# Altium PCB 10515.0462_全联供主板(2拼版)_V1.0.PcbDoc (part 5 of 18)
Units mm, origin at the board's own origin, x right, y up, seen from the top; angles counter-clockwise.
Board outline 282 x 198 mm, 2 copper layers (Top Layer, Bottom Layer); 716 components, 0 nets, 2364 pads, 1800 vias.
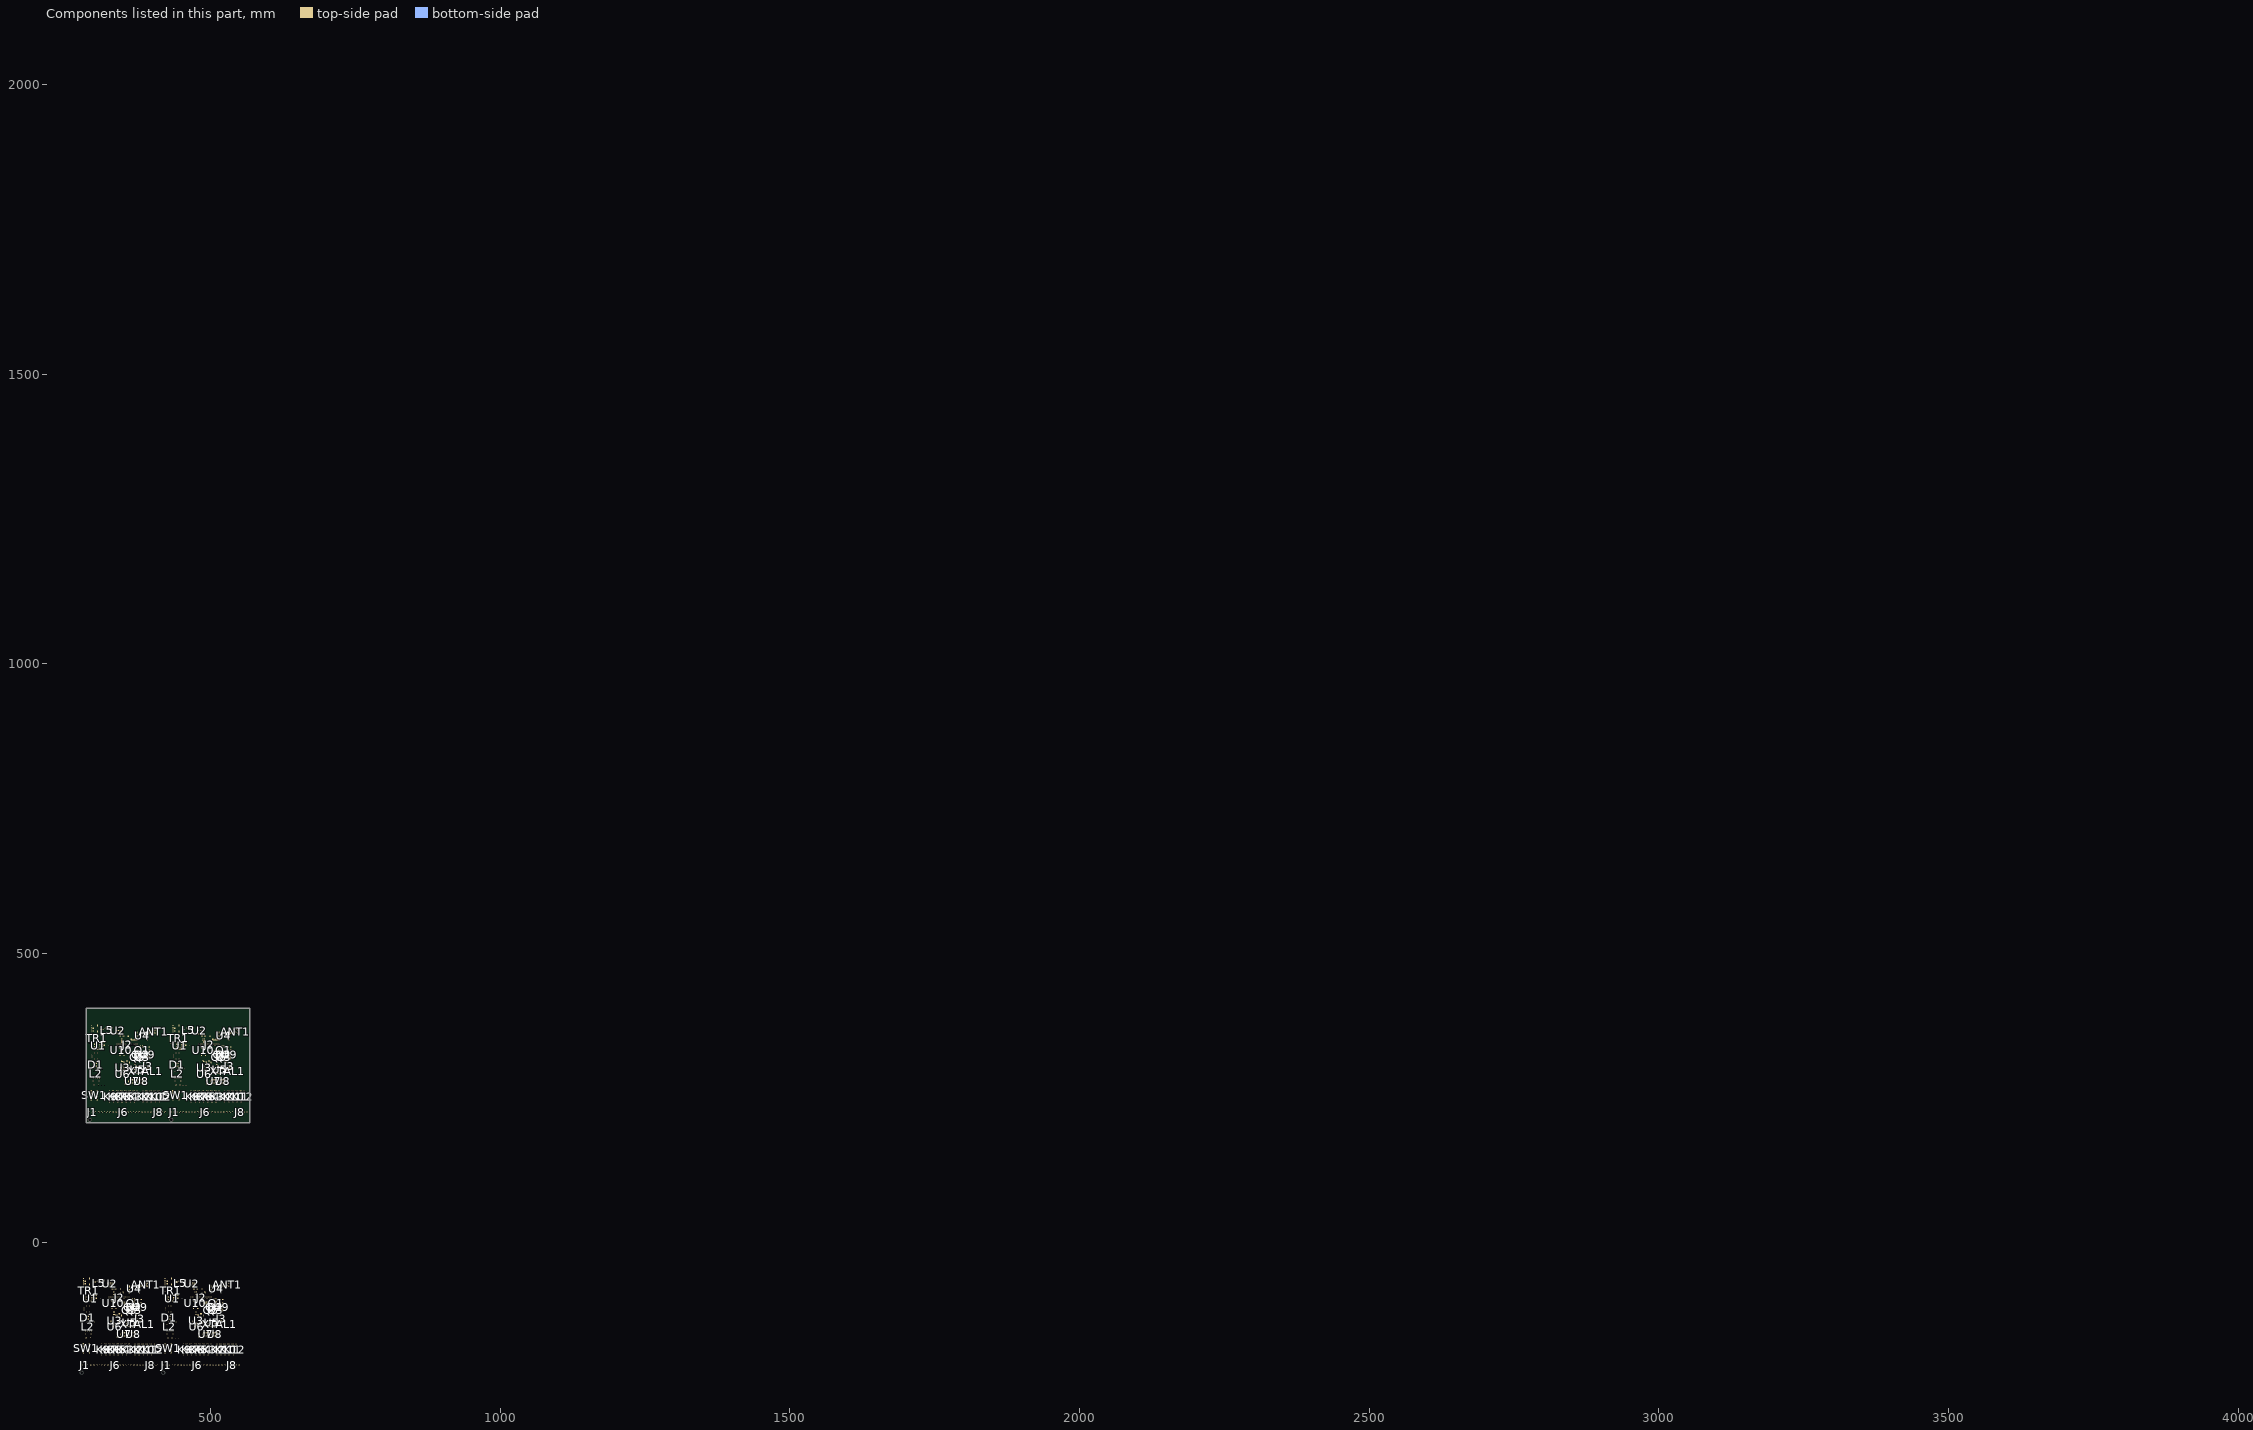
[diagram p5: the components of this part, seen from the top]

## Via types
v1: diameter 0.7, hole 0.4, Top Layer to Bottom Layer, tented both sides, 1800 vias

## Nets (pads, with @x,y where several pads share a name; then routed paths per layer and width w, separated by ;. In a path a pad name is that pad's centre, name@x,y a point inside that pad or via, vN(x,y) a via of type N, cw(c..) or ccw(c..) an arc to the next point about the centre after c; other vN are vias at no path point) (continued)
copper on no net: (continued)
  Top Layer w0.2: 520.272,290.998 ccw(c520.593,291.319) 520.593,290.864 ; 520.328,290.941 cw(c519.945,290.558) 520.487,290.558 ; 520.369,290.9 519.861,291.408 519.099,291.408 518.901,291.607 518.901,292.674 518.901,294.258 519.716,295.074 521.301,295.074 520.732,295.074 ; 520.886,-119.119 cw(c520.363,-119.642) 521.103,-119.642 cw(c521.842,-119.642) 521.319,-119.119 ; v1@521.008,303.473 ccw(c520.404,303.473) 520.831,303.9 ccw(c521.258,304.327) v1@521.258,303.723 ; 521.242,282.672 ccw(c520.815,283.099) 521.419,283.099 ccw(c522.022,283.099) 521.596,282.672 ; 521.301,297.074 524.251,297.074 525.673,295.652 525.991,295.652 526.054,295.652 526.753,296.35 529.674,296.35 529.999,296.025 ; 521.301,297.574 525.719,297.574 ; 521.301,298.074 525.36,298.074 527.411,300.125 527.411,304.577 528.144,305.31 ; 521.301,298.574 525.295,298.574 527.011,300.29 527.011,306.521 527.392,306.902 529.259,306.902 529.532,307.175 529.532,315.284 529.786,315.538 534.339,315.538 534.731,315.931 534.731,317.731 ; 521.301,299.074 525.229,299.074 526.611,300.456 526.611,306.775 527.138,307.302 528.878,307.302 529.132,307.556 529.132,318.84 529.673,319.382 ; 521.301,299.574 525.163,299.574 526.211,300.622 526.211,307.41 526.503,307.702 528.37,307.702 528.732,308.064 528.732,319.456 529.513,320.237 v1(529.513,320.491) ; 521.301,300.074 525.097,300.074 525.811,300.787 525.811,307.645 526.445,308.28 526.445,311.564 ; 521.301,301.074 523.089,301.074 523.329,301.314 523.329,302.603 524.036,303.31 ; 521.301,301.574 522.533,301.574 522.929,301.97 522.929,310.311 522.911,310.329 522.911,314.688 523.488,315.265 527.335,315.265 528.224,316.155 528.224,320.536 528.243,320.555 ; 521.301,302.074 522.11,302.074 522.405,302.369 522.405,303.083 522.401,303.087 522.401,315.03 523.163,315.792 526.465,315.792 526.846,316.173 526.846,320.555 ; 521.301,302.574 521.617,302.574 521.997,302.954 ; 521.929,-133.345 ccw(c521.076,-132.491) 522.283,-132.491 ccw(c523.49,-132.491) 522.637,-133.345 ; 521.966,302.084 ccw(c521.966,302.456) 522.229,302.193 ; 521.974,302.58 cw(c522.197,302.754) 521.997,302.954 ; 522.029,-131.644 cw(c521.416,-132.258) 522.283,-132.258 ; 522.071,-133.486 ccw(c521.559,-132.974) 522.283,-132.974 ccw(c523.007,-132.974) 522.495,-133.486 ; 522.283,-133.571 522.283,-131.517 ; 522.283,-133.378 cw(c524.735,-133.378) 523.001,-131.644 ; 522.283,-132.895 cw(c524.252,-132.895) 522.86,-131.503 ; 522.283,-132.412 cw(c523.769,-132.412) 522.718,-131.362 ; 522.283,-131.93 cw(c523.286,-131.93) 522.577,-131.22 ; 522.413,-71.827 522.554,-71.967 522.579,-71.942 ; 522.512,282.672 ccw(c522.085,283.099) 522.689,283.099 ccw(c523.292,283.099) 522.866,282.672 ; v1@523.417,-74.482 v1@523.631,-74.482 ; 523.448,302.722 cw(c524.036,302.133) 524.036,302.965 ; 523.54,302.814 ccw(c523.082,303.272) 523.729,303.272 ; 523.819,301.404 cw(c523.603,301.187) 523.909,301.187 ; 523.909,300.818 cw(c524.562,300.818) 524.204,301.364 ; 523.909,301.188 cw(c524.319,301.188) 524.094,301.532 ; 524.421,313.215 526.445,313.215 ; 524.688,297.574 cw(c524.688,296.037) 525.774,297.124 ; 524.771,312.965 cw(c525.375,312.361) 525.375,313.215 ; 524.771,313.439 ccw(c525.311,313.978) 525.311,313.215 ; 524.861,296.464 ccw(c525.991,297.594) 525.991,295.996 ccw(c525.991,296.981) 526.687,296.285 ; 524.913,312.823 cw(c525.858,311.878) 525.858,313.215 ; 524.913,313.58 ccw(c525.794,314.461) 525.794,313.215 ; 525.038,325.317 525.356,325 ; 525.17,297.574 cw(c525.17,296.52) 525.916,297.265 ; 525.202,296.123 ccw(c525.991,296.911) 525.991,295.796 ccw(c525.991,296.298) 526.346,295.943 ; 525.544,295.781 ccw(c525.991,296.229) 525.991,295.596 ; 525.653,297.574 cw(c525.653,297.003) 526.057,297.407 ; 525.917,-74.482 526.033,-74.482 ; 526.228,311.309 cw(c525.705,310.786) 526.445,310.786 cw(c527.185,310.786) 526.662,311.309 ; 526.228,312.998 ccw(c525.705,312.475) 525.705,313.215 ccw(c525.705,313.955) 526.228,313.432 ; 526.297,295.69 cw(c526.792,295.69) 526.442,296.039 ; 526.437,322.933 cw(c525.697,322.194) 526.74,322.114 ; 526.629,320.162 cw(c526.106,319.639) 526.846,319.639 cw(c527.586,319.639) 527.063,320.162 ; 526.744,322.625 cw(c526.269,322.15) 526.939,322.099 ; 526.754,322.398 ccw(c526.714,322.523) 526.846,322.523 ccw(c526.978,322.523) 526.938,322.398 ; 527.411,301.303 528.841,301.303 ; 528.026,320.162 cw(c527.548,319.684) 528.224,319.684 ; 528.042,322.337 ccw(c527.66,322.777) 528.243,322.777 ccw(c528.826,322.777) 528.444,322.337 ; 528.224,319.594 cw(c529.028,319.594) 528.46,320.162 ; 528.587,301.086 ccw(c528.063,300.563) 528.063,301.303 ccw(c528.063,302.043) 528.587,301.52 ; 529.212,318.92 cw(c529.987,318.145) 530.077,319.238 ; 529.517,319.226 cw(c530.034,318.709) 530.094,319.437 ; 529.793,319.294 ccw(c529.674,319.258) 529.674,319.382 ; 529.793,319.471 cw(c529.674,319.507) 529.674,319.382 ; 529.819,295.758 ccw(c529.711,296.025) 529.999,296.025 ; v1@529.916,316.625 cw(c529.554,316.235) 530.086,316.235 ; 529.999,295.193 529.999,296.025 ; v1(530.086,316.808) 530.086,316.235 ; 530.086,319.382 529.673,319.382 ; 530.178,295.758 cw(c530.287,296.025) 529.999,296.025 ; v1@530.256,316.625 ccw(c530.618,316.235) 530.086,316.235 ; 530.53,301.341 530.492,301.303 532.277,301.303 ; 530.53,302.947 530.53,303.074 ; 530.656,348.23 cw(c533.417,348.23) 531.465,350.183 ; 530.656,348.713 cw(c532.935,348.713) 531.323,350.324 ; 530.656,349.196 cw(c532.452,349.196) 531.182,350.465 ; 530.656,349.678 cw(c531.969,349.678) 531.04,350.607 ; 530.747,301.086 cw(c531.27,300.563) 531.27,301.303 cw(c531.27,302.043) 530.747,301.52 ; 530.788,350.395 cw(c530.29,350.305) 530.648,349.948 cw(c530.986,349.609) 531.093,350.076 ; 530.833,352.27 ccw(c530.499,352.082) 530.499,352.465 ; 530.833,352.661 cw(c530.499,352.849) 530.499,352.465 ; 530.899,354.183 ccw(c530.216,353.5) 530.216,354.465 ccw(c530.216,355.431) 530.899,354.748 ; 530.899,356.183 ccw(c530.216,355.5) 530.216,356.465 ccw(c530.216,357.431) 530.899,356.748 ; 531.632,352.465 530.499,352.465 ; 531.632,354.465 530.213,354.465 529.767,354.019 529.767,347.288 529.132,346.653 493.572,346.653 493.11,346.191 493.11,345.175 ; 532.023,301.086 ccw(c531.499,300.563) 531.499,301.303 ccw(c531.499,302.043) 532.023,301.52 ; 532.312,302.838 532.312,302.897 532.312,303.024 ; 532.966,317.476 cw(c532.443,316.953) 533.183,316.953 cw(c533.923,316.953) 533.4,317.476 ; 533.183,317.731 533.183,316.415 532.815,316.046 530.275,316.046 530.086,316.235 ; 534.515,317.476 cw(c533.992,316.953) 534.731,316.953 cw(c535.471,316.953) 534.948,317.476 ; 535.558,303.251 ccw(c534.705,304.104) 535.912,304.104 ccw(c537.119,304.104) 536.265,303.251 ; 535.658,304.951 cw(c535.044,304.338) 535.912,304.338 ; 535.7,303.109 ccw(c535.188,303.621) 535.912,303.621 ccw(c536.636,303.621) 536.124,303.109 ; 535.912,303.024 535.912,305.078 ; 535.912,303.217 cw(c538.363,303.217) 536.63,304.951 ; 535.912,303.7 cw(c537.881,303.7) 536.488,305.092 ; 535.912,304.183 cw(c537.398,304.183) 536.347,305.234 ; 535.912,304.666 cw(c536.915,304.666) 536.206,305.375 ; 536.042,364.769 536.182,364.628 536.208,364.654 ; v1@537.046,362.114 v1@537.26,362.114 ; 539.546,362.114 539.661,362.114 ; 323.841,-72.151 324.211,-71.781 ; 325.095,-68.992 325.276,-68.811 ; 338.724,367.603 338.905,367.785 ; 340.721,-110.77 ccw(c340.556,-110.77) 340.622,-110.618 cw(c340.556,-110.77) 340.721,-110.77 ; 340.721,-110.77 cw(c340.886,-110.77) 340.821,-110.618 ccw(c340.886,-110.77) 340.721,-110.77 ; 354.35,325.826 ccw(c354.185,325.826) 354.25,325.977 cw(c354.185,325.826) 354.35,325.826 ; 354.35,325.826 cw(c354.515,325.826) 354.449,325.977 ccw(c354.515,325.826) 354.35,325.826 ; 464.841,-72.151 465.211,-71.781 ; 466.095,-68.992 466.277,-68.811 ; 479.724,367.603 479.905,367.785 ; 481.721,-110.77 ccw(c481.556,-110.77) 481.622,-110.618 cw(c481.556,-110.77) 481.721,-110.77 ; 481.721,-110.77 cw(c481.886,-110.77) 481.821,-110.618 ccw(c481.886,-110.77) 481.721,-110.77 ; 495.35,325.826 ccw(c495.185,325.826) 495.25,325.977 cw(c495.185,325.826) 495.35,325.826 ; 495.35,325.826 cw(c495.515,325.826) 495.449,325.977 ccw(c495.515,325.826) 495.35,325.826
  Top Layer w0.3: v1@339.183,-110.53 cw(c338.841,-110.872) 339.324,-110.872 cw(c339.807,-110.872) v1@339.466,-110.53 ; v1(339.324,-110.389) 339.324,-113.183 339.832,-113.691 347.96,-113.691 348.341,-114.072 v1(348.341,-129.439) ; 346.182,-102.105 346.436,-101.851 346.436,-94.26 ; 346.246,-101.76 ccw(c345.787,-101.301) 346.436,-101.301 ; 346.436,-101.344 ccw(c347.025,-101.344) 346.609,-101.76 ; 346.829,-93.273 cw(c345.486,-93.31) 346.436,-94.26 ; 347.194,-96.305 cw(c346.596,-96.902) 347.441,-96.902 cw(c348.286,-96.902) 347.688,-96.305 ; 347.424,-93.867 ccw(c347.386,-95.21) 346.436,-94.26 ; 347.441,-95.795 347.441,-100.726 347.706,-100.991 349.611,-100.991 349.981,-101.361 ; 347.441,-93.255 346.436,-94.26 ; v1@348.2,-129.298 ccw(c347.858,-128.956) 348.341,-128.956 ccw(c348.824,-128.956) v1@348.483,-129.298 ; 349.369,-93.255 cw(c347.892,-93.255) 348.936,-94.3 cw(c349.981,-95.345) 349.981,-93.867 ; 349.548,-96.228 cw(c348.504,-97.273) 349.981,-97.273 cw(c351.459,-97.273) 350.414,-96.228 ; 349.808,-101.752 ccw(c349.452,-101.361) 349.981,-101.361 ; 349.981,-101.941 349.981,-101.361 ; 349.981,-95.795 349.981,-99.583 350.246,-99.848 356.342,-99.848 356.723,-100.229 356.723,-108.593 355.551,-109.765 ; 349.981,-93.255 348.722,-94.514 348.722,-100.229 348.976,-100.483 353.167,-100.483 353.45,-100.766 353.45,-101.941 ; 350.154,-101.752 cw(c350.51,-101.361) 349.981,-101.361 ; v1@352.811,326.065 cw(c352.47,325.724) 352.953,325.724 cw(c353.436,325.724) v1@353.094,326.065 ; v1(352.953,326.206) 352.953,323.412 353.461,322.904 361.589,322.904 361.97,322.523 v1(361.97,307.156) ; 353.269,-101.76 ccw(c352.831,-101.322) 353.45,-101.322 ccw(c354.069,-101.322) 353.632,-101.76 ; 355.589,-109.509 ccw(c355.589,-108.982) 355.961,-109.355 ; 355.845,-109.765 cw(c356.556,-109.765) 356.053,-109.263 ; 359.811,334.491 360.065,334.745 360.065,342.335 ; 359.875,334.835 ccw(c359.416,335.294) 360.065,335.294 ; 360.065,335.252 ccw(c360.654,335.252) 360.237,334.835 ; 360.458,343.323 cw(c359.115,343.285) 360.065,342.335 ; 360.822,340.291 cw(c360.225,339.693) 361.07,339.693 cw(c361.915,339.693) 361.317,340.291 ; 361.053,342.728 ccw(c361.015,341.385) 360.065,342.335 ; 361.07,340.8 361.07,335.87 361.335,335.604 363.24,335.604 363.61,335.235 ; 361.07,343.34 360.065,342.335 ; v1@361.828,307.298 ccw(c361.487,307.639) 361.97,307.639 ccw(c362.453,307.639) v1@362.111,307.298 ; 362.998,343.34 cw(c361.52,343.34) 362.565,342.295 cw(c363.61,341.251) 363.61,342.728 ; 363.177,340.367 cw(c362.132,339.323) 363.61,339.323 cw(c365.087,339.323) 364.043,340.367 ; 363.437,334.844 ccw(c363.081,335.235) 363.61,335.235 ; 363.61,334.654 363.61,335.235 ; 363.61,340.8 363.61,337.013 363.875,336.747 369.971,336.747 370.352,336.366 370.352,328.003 369.179,326.83 ; 363.61,343.34 362.351,342.081 362.351,336.366 362.605,336.112 366.796,336.112 367.079,335.829 367.079,334.654 ; 363.782,334.844 cw(c364.139,335.235) 363.61,335.235 ; 366.898,334.835 ccw(c366.46,335.273) 367.079,335.273 ccw(c367.698,335.273) 367.26,334.835 ; 369.217,327.086 ccw(c369.217,327.613) 369.59,327.241 ; 369.474,326.83 cw(c370.185,326.83) 369.682,327.333 ; v1@480.183,-110.53 cw(c479.841,-110.872) 480.324,-110.872 cw(c480.807,-110.872) v1@480.466,-110.53 ; v1(480.324,-110.389) 480.324,-113.183 480.832,-113.691 488.96,-113.691 489.341,-114.072 v1(489.341,-129.439) ; 487.182,-102.105 487.436,-101.851 487.436,-94.26 ; 487.246,-101.76 ccw(c486.787,-101.301) 487.436,-101.301 ; 487.436,-101.344 ccw(c488.025,-101.344) 487.609,-101.76 ; 487.829,-93.273 cw(c486.486,-93.31) 487.436,-94.26 ; 488.194,-96.305 cw(c487.596,-96.902) 488.441,-96.902 cw(c489.286,-96.902) 488.688,-96.305 ; 488.424,-93.867 ccw(c488.386,-95.21) 487.436,-94.26 ; 488.441,-95.795 488.441,-100.726 488.706,-100.991 490.611,-100.991 490.981,-101.361 ; 488.441,-93.255 487.436,-94.26 ; v1@489.2,-129.298 ccw(c488.858,-128.956) 489.341,-128.956 ccw(c489.824,-128.956) v1@489.483,-129.298 ; 490.369,-93.255 cw(c488.892,-93.255) 489.936,-94.3 cw(c490.981,-95.345) 490.981,-93.867 ; 490.548,-96.228 cw(c489.504,-97.273) 490.981,-97.273 cw(c492.459,-97.273) 491.414,-96.228 ; 490.808,-101.752 ccw(c490.452,-101.361) 490.981,-101.361 ; 490.981,-101.941 490.981,-101.361 ; 490.981,-95.795 490.981,-99.583 491.246,-99.848 497.342,-99.848 497.723,-100.229 497.723,-108.593 496.551,-109.765 ; 490.981,-93.255 489.722,-94.514 489.722,-100.229 489.976,-100.483 494.167,-100.483 494.45,-100.766 494.45,-101.941 ; 491.154,-101.752 cw(c491.51,-101.361) 490.981,-101.361 ; v1@493.811,326.065 cw(c493.47,325.724) 493.953,325.724 cw(c494.436,325.724) v1@494.094,326.065 ; v1(493.953,326.206) 493.953,323.412 494.461,322.904 502.589,322.904 502.97,322.523 v1(502.97,307.156) ; 494.269,-101.76 ccw(c493.831,-101.322) 494.45,-101.322 ccw(c495.069,-101.322) 494.632,-101.76 ; 496.589,-109.509 ccw(c496.589,-108.982) 496.961,-109.355 ; 496.845,-109.765 cw(c497.556,-109.765) 497.053,-109.263 ; 500.811,334.491 501.065,334.745 501.065,342.335 ; 500.875,334.835 ccw(c500.416,335.294) 501.065,335.294 ; 501.065,335.252 ccw(c501.654,335.252) 501.237,334.835 ; 501.458,343.323 cw(c500.115,343.285) 501.065,342.335 ; 501.822,340.291 cw(c501.225,339.693) 502.07,339.693 cw(c502.915,339.693) 502.317,340.291 ; 502.053,342.728 ccw(c502.015,341.385) 501.065,342.335 ; 502.07,340.8 502.07,335.87 502.335,335.604 504.24,335.604 504.61,335.235 ; 502.07,343.34 501.065,342.335 ; v1@502.828,307.298 ccw(c502.487,307.639) 502.97,307.639 ccw(c503.453,307.639) v1@503.111,307.298 ; 503.998,343.34 cw(c502.52,343.34) 503.565,342.295 cw(c504.61,341.251) 504.61,342.728 ; 504.177,340.367 cw(c503.132,339.323) 504.61,339.323 cw(c506.087,339.323) 505.043,340.367 ; 504.437,334.844 ccw(c504.081,335.235) 504.61,335.235 ; 504.61,334.654 504.61,335.235 ; 504.61,340.8 504.61,337.013 504.875,336.747 510.971,336.747 511.352,336.366 511.352,328.003 510.179,326.83 ; 504.61,343.34 503.351,342.081 503.351,336.366 503.605,336.112 507.796,336.112 508.079,335.829 508.079,334.654 ; 504.782,334.844 cw(c505.139,335.235) 504.61,335.235 ; 507.898,334.835 ccw(c507.46,335.273) 508.079,335.273 ccw(c508.698,335.273) 508.26,334.835 ; 510.217,327.086 ccw(c510.217,327.613) 510.59,327.241 ; 510.474,326.83 cw(c511.185,326.83) 510.682,327.333
  Top Layer w0.4: 327.204,-70.942 327.613,-70.942 328.578,-71.908 328.578,-72.605 ; 327.204,-68.992 328.098,-68.098 330.434,-68.098 330.801,-68.465 330.801,-69.153 ; 327.604,-68.992 cw(c328.57,-68.992) 327.887,-68.309 ; 328.433,-72.459 ccw(c328.08,-72.107) 328.578,-72.107 ccw(c329.077,-72.107) 328.724,-72.459 ; 330.655,-68.969 ccw(c330.303,-68.617) 330.801,-68.617 ccw(c331.299,-68.617) 330.947,-68.969 ; 340.833,365.653 341.241,365.653 342.207,364.687 342.207,363.99 ; 340.833,367.603 341.727,368.497 344.063,368.497 344.43,368.131 344.43,367.442 ; 341.233,367.603 cw(c342.198,367.603) 341.516,368.286 ; 342.061,364.136 ccw(c341.709,364.489) 342.207,364.489 ccw(c342.706,364.489) 342.353,364.136 ; 344.284,367.626 ccw(c343.931,367.979) 344.43,367.979 ccw(c344.928,367.979) 344.576,367.626 ; 468.204,-70.942 468.613,-70.942 469.579,-71.908 469.579,-72.605 ; 468.204,-68.992 469.098,-68.098 471.434,-68.098 471.801,-68.465 471.801,-69.153 ; 468.604,-68.992 cw(c469.57,-68.992) 468.887,-68.309 ; 469.433,-72.459 ccw(c469.08,-72.107) 469.579,-72.107 ccw(c470.077,-72.107) 469.724,-72.459 ; 471.655,-68.969 ccw(c471.303,-68.617) 471.801,-68.617 ccw(c472.299,-68.617) 471.947,-68.969 ; 481.833,365.653 482.241,365.653 483.207,364.687 483.207,363.99 ; 481.833,367.603 482.727,368.497 485.063,368.497 485.43,368.131 485.43,367.442 ; 482.233,367.603 cw(c483.198,367.603) 482.516,368.286 ; 483.061,364.136 ccw(c482.709,364.489) 483.207,364.489 ccw(c483.706,364.489) 483.353,364.136 ; 485.284,367.626 ccw(c484.931,367.979) 485.43,367.979 ccw(c485.928,367.979) 485.576,367.626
